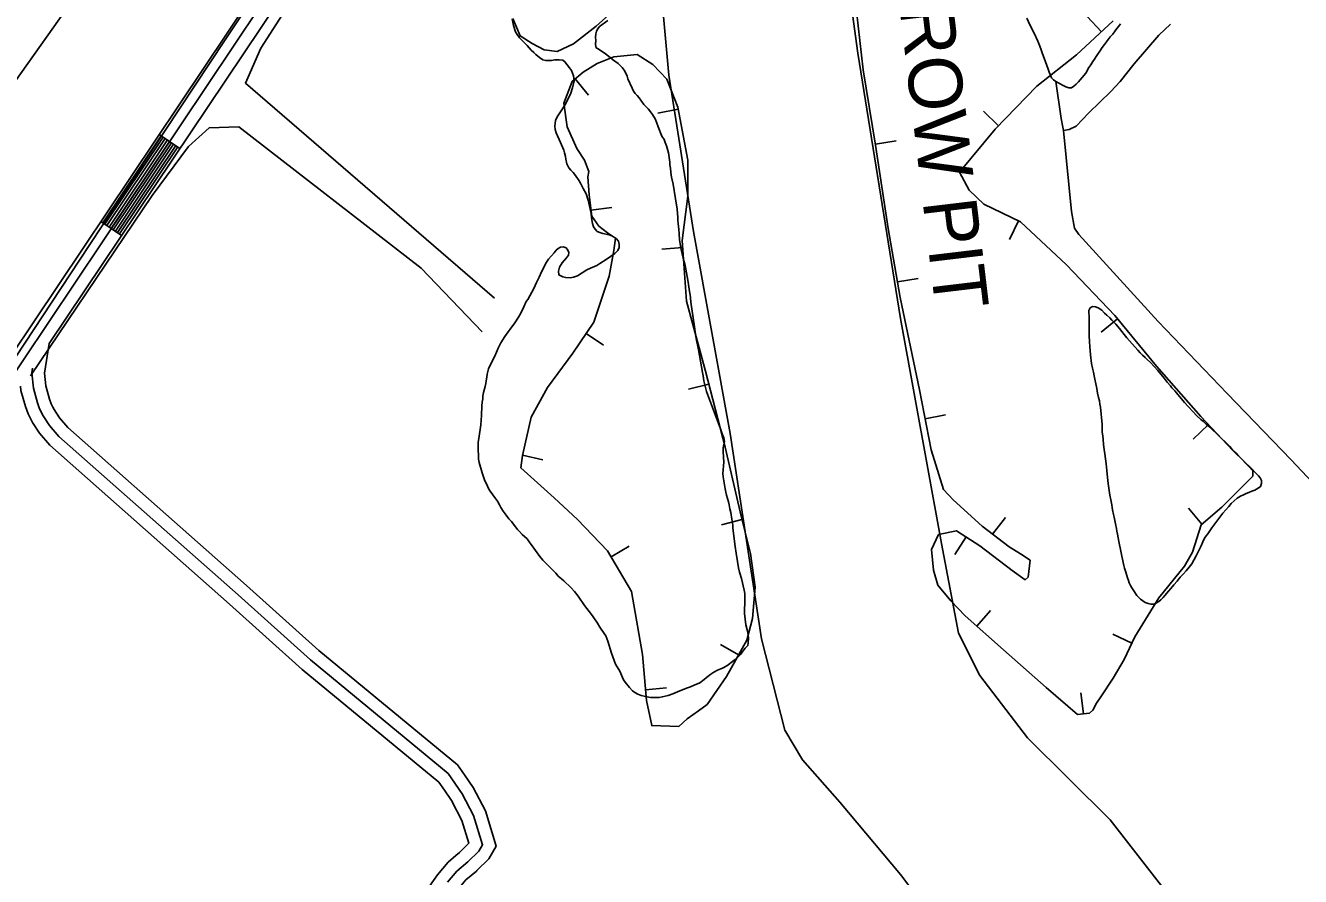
# Model space of a CAD drawing. Extents: x 3161665 to 3199565, y 885729 to 911164.
# Drawn here: x 3182991 to 3184512, y 898552 to 899568 of the extents above; entities that cross this region are included whole.
import ezdxf

# ---------------------------------------------------------------- set-up
doc = ezdxf.new("R2010")
doc.units = 0
for name, color, linetype in [('V-BORW-IDEN', 7, 'Continuous'), ('V-BORW-LINE', 7, 'Continuous'), ('V-LEVE-TOET', 7, 'Continuous'), ('V-ROAD-CNTR', 7, 'Continuous'), ('V-TOPO-SHOR', 7, 'Continuous')]:
    doc.layers.add(name, color=color, linetype=linetype)

msp = doc.modelspace()

# ---------------------------------------------------------------- linework, layer by layer
at = {"layer": 'V-BORW-LINE'}
for p, q in [((3184274.7, 899560.1), (3184257.8, 899578.5)), ((3183646.6, 899503.8), (3183662.6, 899484.6)), ((3183769.8, 899467.7), (3183745.3, 899463)), ((3184151.9, 899447.9), (3184133.9, 899465.3)), ((3184005, 899426), (3184029.7, 899430.1)), ((3183665.6, 899347.3), (3183690.5, 899350.3)), ((3184175.7, 899334.6), (3184164.9, 899312.1)), ((3183775.1, 899302.6), (3183750.2, 899300.8)), ((3184031.5, 899261.5), (3184056.1, 899265.8)), ((3184293.9, 899217.5), (3184274.6, 899201.5)), ((3183660, 899200.1), (3183680.8, 899186.2)), ((3183806.4, 899139.7), (3183782.2, 899133.6)), ((3184064.4, 899098.2), (3184088.9, 899103.1)), ((3184402.5, 899091.2), (3184384.3, 899074)), ((3183584, 899054.6), (3183608.4, 899049)), ((3183845.8, 898977.9), (3183821.6, 898971.7)), ((3184145, 898960.5), (3184160.3, 898980.2)), ((3184394.8, 898972.6), (3184378.5, 898991.5)), ((3184113.5, 898957.1), (3184100, 898936)), ((3183689.6, 898933.5), (3183711.2, 898946.2)), ((3184126.1, 898850.5), (3184142.6, 898869.3)), ((3184311, 898830.5), (3184288.4, 898841.1)), ((3183841.9, 898816.5), (3183820.2, 898828.9)), ((3183730.7, 898774.8), (3183755.6, 898777)), ((3184253.2, 898746.1), (3184250.4, 898771))]:
    msp.add_line(p, q, dxfattribs=at)
for points in [[(3183609.9, 899538.5), (3183625.5, 899536.7), (3183644.7, 899545.6), (3183671.9, 899566.8), (3183702, 899593.7)], [(3183572.5, 899575.9), (3183581.2, 899555.1), (3183595.5, 899546), (3183609.9, 899538.5)], [(3183982.6, 899584.8), (3183990.5, 899514.6), (3184005.2, 899424.7), (3184020.4, 899325.2), (3184034.8, 899242.8), (3184057.5, 899132.9), (3184071.7, 899061.2), (3184086.5, 899013.9), (3184097.9, 899001.3), (3184132.6, 898970.1), (3184164.6, 898945.2), (3184178.1, 898936.9), (3184189.9, 898929.3), (3184187.2, 898909.1), (3184183.7, 898906.1), (3184168.3, 898917.1), (3184129.7, 898946.7), (3184101.8, 898964.6), (3184080.4, 898960), (3184072.1, 898942.2), (3184074.4, 898917.4), (3184079.7, 898899.4), (3184094.9, 898880.8), (3184112.1, 898862.8), (3184157.9, 898822.6), (3184208.7, 898777.4), (3184246.4, 898745.3), (3184260.5, 898746.9), (3184264.5, 898750.2), (3184269.1, 898758.7)], [(3184269.1, 898758.7), (3184274.2, 898766.2), (3184288.8, 898788.5), (3184301.8, 898810.8), (3184314.5, 898837.9), (3184343.1, 898884.3), (3184374, 898922.2), (3184383.6, 898938.8), (3184393.7, 898971.7), (3184418.3, 898992.8), (3184455.4, 899029.6), (3184455.6, 899037.2), (3184431.6, 899060.4), (3184393.3, 899100.9), (3184340.7, 899160.8), (3184290.6, 899221.4), (3184233, 899282), (3184178.4, 899333.3), (3184134.4, 899354.5), (3184117.1, 899370.9), (3184105.4, 899392.6), (3184147.9, 899443.8), (3184197.8, 899495.4), (3184245, 899532.7), (3184288.8, 899573)], [(3183793.9, 898749.4), (3183804.3, 898757.1), (3183827.2, 898790.7), (3183851.8, 898833.9), (3183858.4, 898859.9), (3183861.4, 898897.4), (3183856.1, 898937.5), (3183844.8, 898982), (3183825.6, 899064.2), (3183802.5, 899155.1), (3183779.8, 899238.6), (3183774.5, 899311), (3183781.4, 899364.1), (3183781.4, 899406.7), (3183769.3, 899470.3), (3183756.2, 899503.5), (3183739.6, 899521.2), (3183720.9, 899532.9), (3183693, 899530.4), (3183673, 899522.3), (3183656.3, 899512), (3183643.1, 899500.9), (3183633.3, 899475.1), (3183637.1, 899446.5), (3183648.7, 899421), (3183657.9, 899406.7), (3183663.1, 899393.5), (3183662.1, 899386.8), (3183663.5, 899365.6), (3183666.5, 899340), (3183675, 899328.2), (3183685.3, 899320.2), (3183695.1, 899313.6), (3183693, 899299.1), (3183687.2, 899268.4), (3183668.9, 899213.4), (3183644.2, 899176.6), (3183613.6, 899135.6), (3183594.4, 899100.3), (3183584, 899054.4), (3183581.9, 899039.8), (3183621.6, 899004), (3183649.6, 898978), (3183685.4, 898940.6), (3183714, 898892.2), (3183727, 898816.9), (3183731.8, 898762.1), (3183738.2, 898732), (3183770.4, 898730.8), (3183780.3, 898740), (3183793.9, 898749.4)]]:
    msp.add_lwpolyline(points, dxfattribs=at)
at = {"layer": 'V-LEVE-TOET'}
msp.add_line((3183055.3, 899287.4), (3182907.7, 899064.8), dxfattribs=at)
for points in [[(3184747.1, 898061.1), (3184579.4, 898256.5), (3184440.1, 898420.5), (3184285.2, 898619.3), (3184186.5, 898717.3), (3184129.7, 898791.7), (3184104.3, 898842.4), (3184084, 898949.3), (3184035, 899217.7), (3183984.2, 899534.5), (3183936.9, 899881.1), (3183904.9, 900117.8), (3183885.2, 900211.3), (3183873.7, 900264.9), (3183860.2, 900326.2)], [(3183677.4, 900212.3), (3183549.5, 900040), (3183446.1, 899872), (3183350.8, 899733.7), (3183229, 899550.4), (3183120.9, 899386.8), (3183055.3, 899287.4)], [(3183869.2, 898835.7), (3183831.6, 899080.5), (3183788, 899321.6), (3183758.6, 899508.5), (3183735.9, 899758.4), (3183709.2, 899939.9), (3183677.4, 900212.3)], [(3183062.5, 899619.9), (3182962.8, 899478.5), (3182848.5, 899302.7), (3182780.2, 899189.8), (3182730.9, 899090), (3182696.7, 899036.9), (3182652.8, 898982.5), (3182613.9, 898915.6), (3182576.7, 898825.3), (3182539.5, 898684.6), (3182507.4, 898626.5), (3182486.1, 898585.9), (3182476.3, 898503.7), (3182458.1, 898457.8), (3182435.4, 898425), (3182418.2, 898372.9), (3182390.8, 898259.3), (3182366.4, 898162.3)], [(3184377.4, 898104.4), (3184266.8, 898249.5), (3184199.5, 898336.4), (3184111.6, 898452.3), (3184035.2, 898554.1), (3183962.5, 898640.6), (3183918.2, 898691), (3183897, 898726.7), (3183869.2, 898835.7)]]:
    msp.add_lwpolyline(points, dxfattribs=at)
at = {"layer": 'V-ROAD-CNTR'}
for p, q in [((3183150.2, 899437.7), (3183175.1, 899421)), ((3183080.6, 899333.8), (3183105.6, 899317.1))]:
    msp.add_line(p, q, dxfattribs=at)
for points in [[(3182187, 897012.2), (3182302.6, 897572.9), (3182360.8, 897893.4), (3182452, 898273.4), (3182534, 898509.2), (3182687.4, 898899.6), (3182712.2, 898948.6), (3182738.2, 898979.1), (3182754.5, 898992.7), (3182780.9, 899014.2), (3182813.4, 899037.6), (3182842.8, 899053.6), (3182870.3, 899066), (3182891.3, 899078.2), (3182911.2, 899094.7), (3182932.2, 899115.9), (3182943.9, 899129.6), (3183289.6, 899645.8), (3183531.4, 899977.6), (3183646.8, 900106), (3183737.5, 900204.9)], [(3183019.3, 899188.2), (3183314.2, 899628.6), (3183554.8, 899958.6), (3183669.1, 900085.9), (3183758.9, 900183.8)], [(3183301.9, 899637.2), (3182955.9, 899120.5), (3182943.2, 899105.7), (3182921.4, 899083.6), (3182899.9, 899065.9), (3182877.2, 899052.6), (3182849.5, 899040.1), (3182821.4, 899024.9), (3182790, 899002.3), (3182764.1, 898981.2), (3182748.8, 898968.4), (3182724.8, 898940.3), (3182701.1, 898893.4), (3182548, 898504), (3182466.4, 898269.1), (3182375.4, 897890.4), (3182317.3, 897570), (3182201.7, 897009.2)], [(3183083.1, 899332.1), (3183152.7, 899436)], [(3183085.6, 899330.5), (3183155.2, 899434.3)], [(3183088.1, 899328.8), (3183157.7, 899432.6)], [(3183090.6, 899327.1), (3183160.2, 899431)], [(3183093.1, 899325.4), (3183162.7, 899429.3)], [(3183095.6, 899323.8), (3183165.1, 899427.6)], [(3183098.1, 899322.1), (3183167.6, 899426)], [(3183100.6, 899320.4), (3183170.1, 899424.3)], [(3183103.1, 899318.8), (3183172.6, 899422.6)], [(3183019.3, 899188.2), (3183013.6, 899152.7), (3183015.1, 899137.6), (3183019.4, 899121.8), (3183021.5, 899116), (3183023.6, 899111.9)], [(3182999.3, 899158.6), (3182998.5, 899153.2), (3183000.3, 899134.9), (3183005.1, 899117.4), (3183007.7, 899110), (3183012.1, 899101.6), (3183019.6, 899090.2), (3183030.7, 899077.1), (3183244.5, 898888.1), (3183331, 898810.3), (3183495.2, 898674.8), (3183512.1, 898650.4), (3183525.6, 898624.5), (3183536.3, 898589.8), (3183531.9, 898582.2), (3183518.8, 898569.4), (3183505.7, 898558.3), (3183494.3, 898545)], [(3182985, 899137.1), (3182985.5, 899132.1), (3182990.8, 899112.9), (3182993.9, 899104), (3182998.1, 899096)], [(3183023.6, 899111.9), (3183025.1, 899109.2), (3183031.6, 899099.2), (3183041.4, 899087.6), (3183254.5, 898899.3), (3183340.8, 898821.6), (3183506.3, 898685), (3183514.6, 898673.1)], [(3182998.1, 899096), (3182999.2, 899093.9), (3183007.5, 899081.2), (3183020, 899066.6), (3183234.5, 898876.9), (3183321.2, 898798.9), (3183484, 898664.5), (3183490.7, 898655)], [(3183514.6, 898673.1), (3183524.9, 898658.2), (3183539.6, 898630.3), (3183552.5, 898588), (3183543.9, 898572.9), (3183529.4, 898558.9)], [(3183490.7, 898655), (3183499.2, 898642.6), (3183511.7, 898618.8), (3183520, 898591.6), (3183519.9, 898591.5), (3183508.7, 898580.5), (3183504.3, 898576.8)], [(3183504.3, 898576.8), (3183495.1, 898568.9), (3183482.4, 898554), (3183473.1, 898540.4), (3183387.2, 898348.6), (3183365.4, 898268.1), (3183354.3, 898213.9), (3183353.6, 898210.1)], [(3183529.4, 898558.9), (3183528.9, 898558.3), (3183516.3, 898547.7), (3183506.3, 898535.9), (3183499.4, 898525.8), (3183415.5, 898338.5), (3183394.6, 898261.1), (3183383.7, 898208.1), (3183382.4, 898200.9)]]:
    msp.add_lwpolyline(points, dxfattribs=at)
at = {"layer": 'V-TOPO-SHOR'}
for points in [[(3183499.6, 899871.6), (3183377.8, 899706.1), (3183271.7, 899540.5), (3183253.3, 899498.8), (3183550.4, 899242.3)], [(3183571.5, 899575.4), (3183573.1, 899567.5), (3183575.5, 899560.1), (3183577.7, 899556.7), (3183580.3, 899553), (3183589.4, 899543.6), (3183594.4, 899538), (3183597.6, 899535.3), (3183599.9, 899533.1), (3183604.3, 899529.3), (3183608.1, 899526.7), (3183611.7, 899525.7), (3183618.4, 899525.9), (3183622.6, 899526.5), (3183627.8, 899526.7), (3183632, 899526.1), (3183634.5, 899524.3), (3183640.1, 899517), (3183642.3, 899513.8), (3183644.9, 899507.4), (3183645.7, 899501.5), (3183643.5, 899493.3), (3183641.1, 899485.6), (3183634.3, 899472.4), (3183629.2, 899464.5), (3183625.2, 899458.7), (3183623.4, 899454.1), (3183622.4, 899447.6), (3183622.8, 899443.6), (3183624.2, 899439.4), (3183629.4, 899428.1), (3183633.1, 899418.9), (3183634.1, 899415.8), (3183635.3, 899411.4), (3183635.7, 899408.2), (3183636.9, 899402.6), (3183639.3, 899397.7), (3183641.7, 899394.9), (3183644.5, 899392.1), (3183647.1, 899388.7), (3183651.6, 899382.2), (3183653.2, 899379.6), (3183656.4, 899373.2), (3183660, 899366.5), (3183662.2, 899359.3), (3183665.7, 899343.4), (3183666.1, 899338.2), (3183667.5, 899331.1), (3183668.7, 899327.3), (3183670.5, 899324.7), (3183673.1, 899321.9), (3183676.1, 899320.7), (3183679.7, 899319.5), (3183687.4, 899317.7)], [(3183674.3, 899539.7), (3183671.9, 899540.8), (3183671.1, 899545), (3183671.3, 899550.2), (3183671.1, 899553.3), (3183671.3, 899557.5), (3183672.3, 899560.7), (3183673.9, 899563.5), (3183675.9, 899566.5), (3183685.8, 899573.6)], [(3184211.4, 899515.7), (3184206.5, 899528.7), (3184204.6, 899533.7), (3184203, 899538.4), (3184201.1, 899543.1), (3184198.8, 899548.9), (3184194.4, 899558.6), (3184189.6, 899567.6), (3184185.8, 899576.5)], [(3184297.7, 899569.5), (3184295.5, 899566.7), (3184293.2, 899563.9), (3184291.1, 899561.3), (3184288.3, 899557.3), (3184285.4, 899554), (3184282.7, 899550.9), (3184280.9, 899548.3), (3184278.4, 899544.9), (3184275.8, 899541.3), (3184272.8, 899537.1), (3184270.3, 899533.2), (3184268.6, 899530.7), (3184266.5, 899527.3), (3184264.7, 899524.5), (3184262, 899520.5), (3184259.9, 899517.3), (3184256, 899510.7), (3184251.8, 899505.4), (3184249.5, 899502.8), (3184247.3, 899500.3), (3184244.7, 899497.6), (3184241.7, 899495.1), (3184238.9, 899493.2), (3184235.8, 899493.1), (3184232.4, 899494.4), (3184229.3, 899496), (3184220.4, 899500.9), (3184217.7, 899502.6), (3184215.4, 899505.3), (3184213.6, 899509.2), (3184212.6, 899512), (3184211.4, 899515.7)], [(3184220.4, 899500.9), (3184226.8, 899456.8), (3184228.9, 899446.2), (3184229.5, 899442.4), (3184236.4, 899443.5), (3184244.5, 899447.5), (3184259.8, 899463.3), (3184286.2, 899488.9), (3184297.3, 899500.9), (3184313.7, 899521.9), (3184343.1, 899555.9), (3184357.1, 899569.3)], [(3183849.8, 898824.4), (3183853, 898827.6), (3183853.4, 898830.6), (3183853.8, 898836.6), (3183852.8, 898842.7), (3183852, 898846.3), (3183850.4, 898852.1), (3183849, 898865.6), (3183849, 898868.8), (3183848.8, 898872), (3183849.2, 898876.5), (3183849.4, 898889.7), (3183848.6, 898893.8), (3183845.4, 898907.4), (3183842.9, 898915.3), (3183841.7, 898920.3), (3183840.7, 898927.8), (3183838.9, 898937.6), (3183837.7, 898945.9), (3183834.9, 898967.8), (3183834.9, 898971.2), (3183833.9, 898978.5), (3183832.5, 898986.5), (3183831.5, 898990.9), (3183830.7, 898995.6), (3183829.9, 898999), (3183827.4, 899007), (3183826.6, 899010.5), (3183825.8, 899014.7), (3183823.6, 899029), (3183823.2, 899033), (3183824.2, 899046.3), (3183823.6, 899058.9), (3183823.6, 899063.4), (3183824.8, 899071), (3183824.2, 899075.4), (3183822.4, 899080.3), (3183820.4, 899086.3), (3183803.7, 899130.6), (3183802.7, 899133.8), (3183800.4, 899143.4), (3183799.4, 899149.6), (3183798.6, 899153.3), (3183794.1, 899180.6), (3183791.3, 899194.2), (3183790.4, 899199.2), (3183789, 899210.6), (3183787.7, 899218.6), (3183785, 899237.2), (3183784.5, 899242.7), (3183783.9, 899246.3), (3183783.1, 899250.1), (3183782, 899258.4), (3183781.2, 899263.5), (3183778, 899281), (3183775.8, 899290.1), (3183773.2, 899300.3), (3183771.9, 899307.2), (3183771.4, 899311.8), (3183771, 899319.2), (3183770.4, 899324.1), (3183769.7, 899331.2), (3183769.5, 899335.3), (3183769.5, 899338.6), (3183768.4, 899348.4), (3183766.5, 899360.7), (3183763.7, 899378.1), (3183761.9, 899386.5), (3183761, 899392), (3183760.4, 899397.2), (3183759.8, 899401.3), (3183759.8, 899404.4), (3183758, 899415.6), (3183755.7, 899424), (3183754.3, 899428), (3183752.9, 899431.4), (3183750.2, 899435.7), (3183745.9, 899446.7), (3183744, 899452.1), (3183742.1, 899456.2), (3183739.2, 899461.2), (3183736.8, 899464.4), (3183734.1, 899468), (3183730.9, 899471.5), (3183728.6, 899473.5), (3183725.8, 899477.2), (3183723.3, 899481.3), (3183720.9, 899484.1), (3183718.4, 899486.6), (3183716.6, 899489.4), (3183714.7, 899492.7), (3183709.8, 899503.8), (3183708.8, 899507.1), (3183707, 899511.6), (3183705.4, 899514.3), (3183703, 899517.4), (3183698.3, 899522.3), (3183691.4, 899527.1), (3183688.7, 899529.5), (3183683, 899534), (3183674.3, 899539.7)], [(3183535.9, 899201.9), (3183463, 899277.8), (3183245.4, 899446.6), (3183210.2, 899445.4), (3183185.3, 899423.3), (3183142.1, 899364.6), (3182996.8, 899149.6)], [(3184589.7, 898955.2), (3184501.4, 899049.3), (3184424.9, 899128.3), (3184342.3, 899214.4), (3184247.8, 899318), (3184242.5, 899325.8), (3184239.1, 899345.5), (3184229.5, 899442.4)], [(3183687.4, 899317.7), (3183690.6, 899316.5), (3183695.6, 899313.4), (3183698.5, 899310.2), (3183699.5, 899306.4), (3183699.5, 899302.8), (3183697.9, 899299.1), (3183694, 899295.5), (3183683.8, 899288.5), (3183676.1, 899283.5), (3183672.7, 899281.2), (3183669.9, 899279.8), (3183664.9, 899277.8), (3183660.8, 899275.8), (3183649.4, 899269), (3183644.9, 899267.4), (3183640.9, 899266.6), (3183635.5, 899266.8), (3183632.1, 899267.6), (3183627.4, 899270), (3183626.8, 899274.4), (3183628.2, 899279), (3183631.3, 899284.5), (3183636.5, 899290.5), (3183638.7, 899293.5), (3183639.3, 899296.7), (3183638.1, 899299.5), (3183635.9, 899302.2), (3183632.5, 899303.6), (3183629.4, 899303.2), (3183626.6, 899301.6), (3183624, 899299.3), (3183621.6, 899296.3), (3183615, 899288.7), (3183612.5, 899285.1), (3183606.5, 899273.6), (3183603.7, 899267.2), (3183600.5, 899260.7), (3183597.5, 899253.9), (3183590.2, 899240.6), (3183588.4, 899238), (3183585.4, 899231.9), (3183582, 899224.3), (3183579.2, 899219.3), (3183574.9, 899212.8), (3183569.1, 899205), (3183566.9, 899202), (3183562.7, 899196.5), (3183558, 899188.9), (3183554.8, 899182.4), (3183551, 899173), (3183544.6, 899160.5), (3183543.3, 899157.7), (3183541.7, 899151.3), (3183541.5, 899148), (3183540.7, 899143.6), (3183540.3, 899140.4), (3183539.5, 899136.8), (3183537.3, 899129.5), (3183536.7, 899125.5), (3183536.5, 899121.9), (3183535.9, 899117.9), (3183535.5, 899113.8), (3183534.9, 899102.2), (3183534.1, 899090.9), (3183531.9, 899074.8), (3183531.1, 899070.4), (3183530.9, 899061.9), (3183531.5, 899053.5), (3183531.5, 899050.1), (3183532.1, 899046), (3183535.9, 899033.8), (3183538.7, 899025.5), (3183542.2, 899017.7), (3183543.8, 899014.3), (3183545.4, 899011.6), (3183551.8, 899003), (3183554, 898999.8), (3183556.4, 898995.5), (3183558, 898992.3), (3183560.9, 898988.1), (3183564.5, 898983.1), (3183567.7, 898978.8), (3183570.9, 898975.4), (3183572.7, 898973), (3183575.4, 898969.2), (3183577.8, 898966.2), (3183580.2, 898963.8), (3183583.4, 898960.1), (3183589.4, 898954.7), (3183592.1, 898951.5), (3183594.1, 898948.3), (3183604.7, 898933.8), (3183608.1, 898929.6), (3183614, 898923.3), (3183623.6, 898913.9), (3183626.7, 898910.2), (3183630.3, 898907), (3183633.3, 898904.6), (3183641.5, 898897), (3183646, 898891.9)], [(3184295.4, 898951.9), (3184294, 898960.4), (3184293.3, 898963.9), (3184292.9, 898967.2), (3184291.6, 898972.9), (3184289.9, 898980.6), (3184289.2, 898984), (3184288.2, 898989.4), (3184287.7, 898992.4), (3184287.2, 898995.4), (3184285.9, 899001.5), (3184284.9, 899007), (3184283.2, 899018.1), (3184282.4, 899024.1), (3184281.4, 899036.4), (3184280.4, 899044.3), (3184278.8, 899056.2), (3184278.1, 899061.4), (3184277.4, 899067.3), (3184276.7, 899073.4), (3184276.4, 899077.8), (3184275.8, 899082.2), (3184275.5, 899091.3), (3184274.9, 899099.6), (3184274.4, 899103.8), (3184273.7, 899112.2), (3184273, 899115.8), (3184272.4, 899119.7), (3184271.4, 899123.7), (3184270.3, 899128.9), (3184269.3, 899134.4), (3184268.1, 899139.8), (3184267, 899145.3), (3184266.1, 899149.5), (3184265.3, 899153.9), (3184264.1, 899158.7), (3184263, 899164.3), (3184261.7, 899174.6), (3184261.2, 899179.5), (3184260.8, 899184.1), (3184260.4, 899190.5), (3184260.3, 899197.3), (3184260.2, 899201.7), (3184260.1, 899207.3), (3184260.1, 899212.8), (3184260, 899216.7), (3184260, 899221), (3184259.8, 899224.2), (3184259.9, 899227.5), (3184261.4, 899230.6), (3184264.1, 899232.2), (3184267.7, 899231.8), (3184270.8, 899230.8), (3184275.1, 899227.7), (3184278.3, 899224.4), (3184281.4, 899221.7), (3184284.7, 899218.7), (3184287.2, 899216.1), (3184291.9, 899211.1), (3184296.2, 899205.8), (3184299, 899202.5), (3184301.9, 899198.9), (3184305.3, 899194.8), (3184318.2, 899179.9), (3184321.2, 899177.1), (3184324, 899174.2), (3184326.8, 899171.5), (3184329.4, 899169.1), (3184333.3, 899165.4), (3184337.7, 899160.6), (3184342, 899156), (3184345.5, 899151.6), (3184349.5, 899146.7), (3184353.4, 899141.9), (3184357.1, 899137.6), (3184359, 899135.2), (3184362.3, 899131.4), (3184364.5, 899129), (3184371.8, 899120.2), (3184373.9, 899117.8), (3184388.8, 899101.7), (3184393.6, 899097.5), (3184396.6, 899094.8), (3184399.8, 899091.9), (3184404.1, 899088), (3184408.1, 899084.4), (3184411.6, 899081.1), (3184414.9, 899078), (3184418.6, 899074.4), (3184422.4, 899070.8), (3184424.6, 899068.5), (3184427.9, 899065.1), (3184429.9, 899062.7), (3184433.3, 899059.2), (3184435.5, 899057), (3184438.5, 899053.9), (3184442.6, 899049.4), (3184446.4, 899045.5), (3184449.5, 899042.6), (3184453.2, 899039), (3184456.4, 899035.9)], [(3184456.4, 899035.9), (3184459.7, 899032.6), (3184462.2, 899030), (3184464.3, 899027.8), (3184465.7, 899024.7), (3184465.8, 899021.1), (3184464.6, 899017.2), (3184461.9, 899015.2), (3184457.7, 899013.1), (3184454.2, 899011.7), (3184450.7, 899010.4), (3184447.6, 899008.9), (3184444.5, 899007.6), (3184440.6, 899005.9), (3184436.9, 899003.4), (3184433.3, 899000.4), (3184429.8, 898996.9), (3184427, 898993.6), (3184419.8, 898985.4), (3184406.6, 898968.2), (3184403.4, 898963.4), (3184401.6, 898960.8), (3184399.7, 898958.3), (3184397.8, 898955.5), (3184395.7, 898951.2), (3184393.8, 898946.5), (3184388, 898934.7), (3184382.7, 898925), (3184379.4, 898921.2), (3184376, 898916.9), (3184372.2, 898912.6), (3184368.9, 898909.1), (3184365, 898904.5), (3184361.3, 898900), (3184357.7, 898895.8), (3184354.8, 898892.4), (3184350.5, 898887.1), (3184348.4, 898884.8), (3184345.5, 898882), (3184343.3, 898879.9), (3184337.8, 898877), (3184333.9, 898877.1), (3184330.5, 898877.8), (3184327.1, 898879.1), (3184324.3, 898880.8), (3184321.6, 898882.9), (3184317.2, 898887.4), (3184312.7, 898894), (3184311, 898896.5), (3184309.4, 898899.3), (3184308, 898902.3), (3184307, 898905.1), (3184305.8, 898908.4), (3184303.8, 898915), (3184302.5, 898920), (3184301.7, 898923), (3184300.9, 898926.6), (3184295.4, 898951.9)], [(3183646, 898891.9), (3183650.4, 898886.3), (3183657.8, 898875.2), (3183666.3, 898864.4), (3183668.3, 898861.6), (3183673.3, 898854.1), (3183676.2, 898849.5), (3183681.6, 898842), (3183683.2, 898839.2), (3183685.6, 898832.6), (3183690.2, 898818.5), (3183695.1, 898805.2), (3183699.9, 898797), (3183703.1, 898789.5), (3183704.5, 898786.7), (3183706.3, 898783.7), (3183711.6, 898777.3), (3183715.4, 898773.4), (3183717.8, 898771.6), (3183721.4, 898769.6), (3183725.5, 898768), (3183732.9, 898766.2), (3183736.7, 898765.6), (3183743.6, 898765.6), (3183747, 898765.6), (3183750.8, 898766.2), (3183754, 898767), (3183757.8, 898768), (3183763.3, 898770), (3183771.7, 898773.6), (3183774.7, 898774.7), (3183779.8, 898776.5), (3183784.6, 898778.3), (3183789, 898780.1), (3183795.5, 898783.1), (3183800.9, 898787.1), (3183803.5, 898789.3), (3183808.5, 898793.2), (3183812.4, 898795.6), (3183816.8, 898798), (3183822.6, 898800.6), (3183827.7, 898803.2), (3183836.3, 898809.5), (3183838.9, 898811.5), (3183844.4, 898817.1), (3183846.8, 898820.7), (3183849.8, 898824.4)]]:
    msp.add_lwpolyline(points, dxfattribs=at)

# ---------------------------------------------------------------- texts
at = {"layer": 'V-BORW-IDEN'}
msp.add_text('BORROW PIT', height=64, rotation=276.8057, dxfattribs=at).set_placement((3184011.8, 899773.3))

doc.saveas('drawing.dxf')
